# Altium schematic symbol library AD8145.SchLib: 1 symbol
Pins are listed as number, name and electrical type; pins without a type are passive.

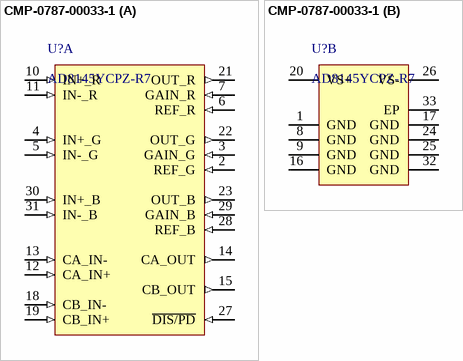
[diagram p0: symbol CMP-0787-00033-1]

## CMP-0787-00033-1
designator U?, comment AD8145YCPZ-R7
High Speed, Triple Differential Receiver with Comparator, 4.5 to 11 V Supply, 500 MHz Bandwidth, Industrial, 32-pin QFN (CP-32-3), Reel; Manufacturer: Analog Devices; -3dB Bandwidth: 500MHz, 425MHz; Max Pos Supply: 11V, 11V; Minimum Gain (Acl): 1; Slew Rate (V/us): 2100, 2000; 0.1 dB Flatness (MHz): 75, 53; Min Pos Supply: 4.5V, 4.5V
footprint ADI-CP-32-3_M (QFN, 32-Leads, Body 5x5mm, Pitch 0.5mm, Thermal Pad 3.3x3.3mm, IPC Low Density)
footprint ADI-CP-32-3_N (QFN, 32-Leads, Body 5x5mm, Pitch 0.5mm, Thermal Pad 3.3x3.3mm, IPC Medium Density)
footprint ADI-CP-32-3_L (QFN, 32-Leads, Body 5x5mm, Pitch 0.5mm, Thermal Pad 3.3x3.3mm, IPC High Density)
part A pins: 2 REF_G (in) "Reference Input, Green Channel.", 3 GAIN_G (in) "Gain Connection, Green Channel.", 4 IN+_G (in) "Noninverting Input, Green Channel.", 5 IN-_G (in) "Inverting Input, Green Channel.", 6 REF_R (in) "Reference Input, Red Channel.", 7 GAIN_R (in) "Gain Connection, Red Channel.", 10 IN+_R (in) "Noninverting Input, Red Channel.", 11 IN-_R (in) "Inverting Input, Red Channel.", 12 CA_IN+ (in) "Positive Input, Comparator A.", 13 CA_IN- (in) "Negative Input, Comparator A.", 14 CA_OUT (out) "Output, Comparator A.", 15 CB_OUT (out) "Output, Comparator B.", 18 CB_IN- (in) "Negative Input, Comparator B.", 19 CB_IN+ (in) "Positive Input, Comparator B.", 21 OUT_R (out) "Output, Red Channel.", 22 OUT_G (out) "Output, Green Channel.", 23 OUT_B (out) "Output, Blue Channel.", 27 ~{DIS/PD} (in) "Disable/Power Down.", 28 REF_B (in) "Reference Input, Blue Channel.", 29 GAIN_B (in) "Gain Connection, Blue Channel.", 30 IN+_B (in) "Noninverting Input, Blue Channel.", 31 IN-_B (in) "Inverting Input, Blue Channel."
part B pins: 1 GND (power) "Signal Ground and Thermal Plane Connection. (See the Absolute Maximum Ratings section.)", 8 GND (power) "Signal Ground and Thermal Plane Connection. (See the Absolute Maximum Ratings section.)", 9 GND (power) "Signal Ground and Thermal Plane Connection. (See the Absolute Maximum Ratings section.)", 16 GND (power) "Signal Ground and Thermal Plane Connection. (See the Absolute Maximum Ratings section.)", 17 GND (power) "Signal Ground and Thermal Plane Connection. (See the Absolute Maximum Ratings section.)", 20 VS+ (power) "Positive Power Supply.", 24 GND (power) "Signal Ground and Thermal Plane Connection. (See the Absolute Maximum Ratings section.)", 25 GND (power) "Signal Ground and Thermal Plane Connection. (See the Absolute Maximum Ratings section.)", 26 VS- (power) "Negative Power Supply.", 32 GND (power) "Signal Ground and Thermal Plane Connection. (See the Absolute Maximum Ratings section.)", 33 EP (power) "Signal Ground and Thermal Plane Connection."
